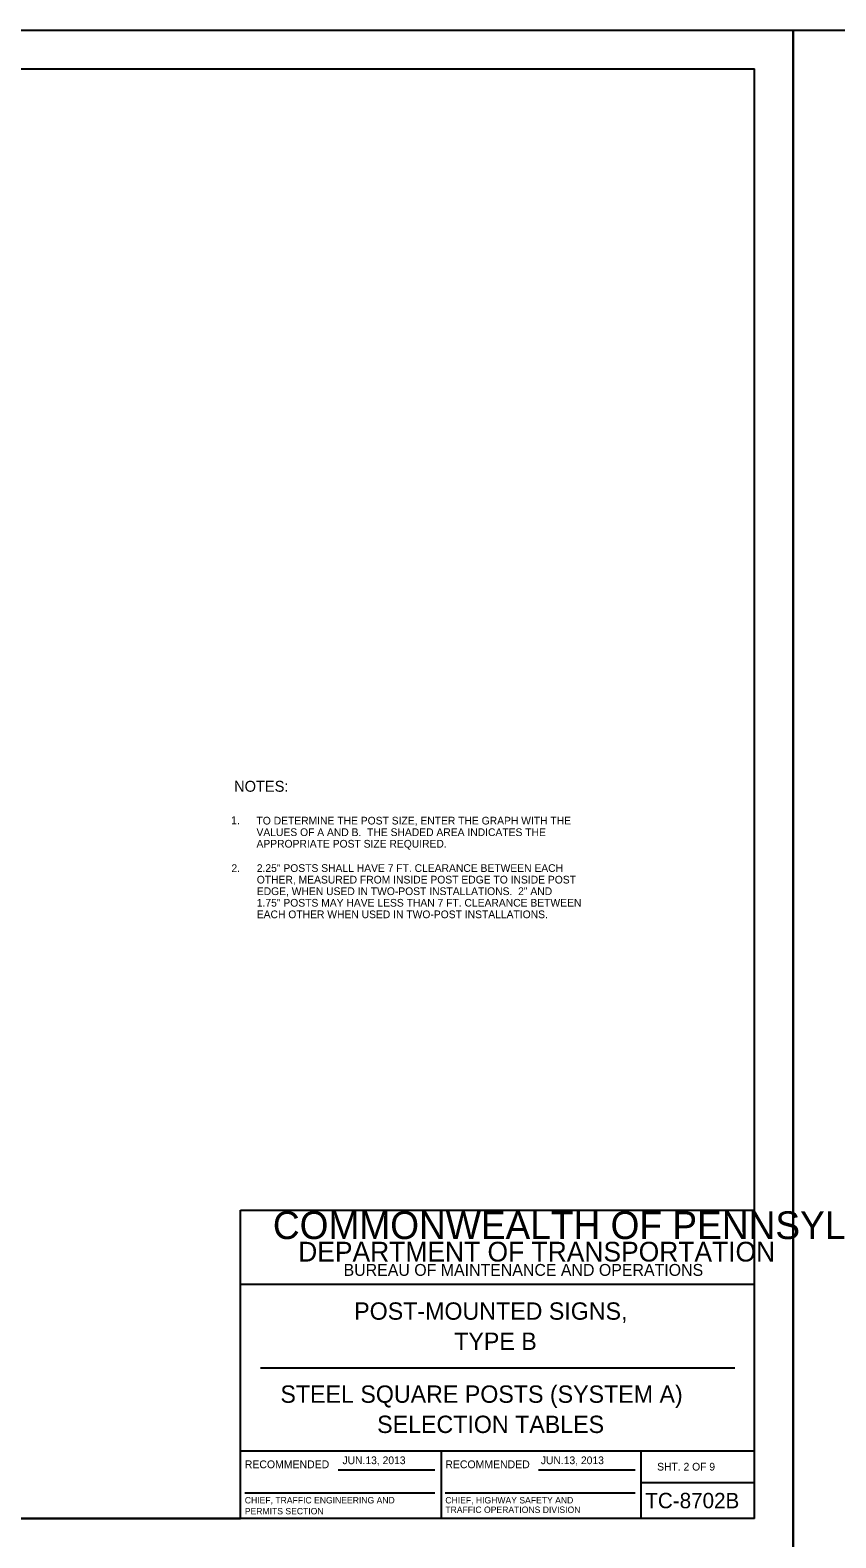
# Model space of a CAD drawing. Extents: x 644358 to 648627, y 294594 to 295782.
# Drawn here: x 645743 to 646057, y 295195 to 295782 of the extents above; entities that cross this region are included whole.
import ezdxf

# ---------------------------------------------------------------- set-up
doc = ezdxf.new("R2010")
doc.units = 0
for name, color, linetype in [('1', 7, 'Continuous'), ('2', 7, 'Continuous'), ('4', 7, 'Continuous'), ('PLT-BNDY', 7, 'Continuous')]:
    doc.layers.add(name, color=color, linetype=linetype)

msp = doc.modelspace()

# ---------------------------------------------------------------- linework, layer by layer
at = {"layer": '1'}
for p, q in [((645239.31, 295766.63), (646025.31, 295766.63)), ((646025.31, 295202.63), (646025.31, 295766.63)), ((645825.31, 295202.63), (645825.31, 295322.63)), ((645825.31, 295322.63), (646025.31, 295322.63)), ((646025.31, 295293.63), (645825.31, 295293.63)), ((645833.06, 295261.31), (646017.56, 295261.31)), ((645825.31, 295229), (646025.31, 295229)), ((645903.31, 295229), (645903.31, 295202.63)), ((645981.19, 295202.63), (645981.19, 295229)), ((645863.24, 295221.57), (645900.87, 295221.57)), ((645941.24, 295221.57), (645978.87, 295221.57)), ((645981.19, 295216.63), (646025.31, 295216.63)), ((645826.99, 295212.68), (645900.87, 295212.68)), ((645904.99, 295212.68), (645978.87, 295212.68)), ((646025.31, 295202.63), (645239.31, 295202.63)), ((645239.31, 295202.63), (645825.31, 295202.63))]:
    msp.add_line(p, q, dxfattribs=at)
at = {"layer": 'PLT-BNDY'}
for points in [[(645199.31, 295781.63), (646040.31, 295781.63), (646040.31, 295187.63), (645199.31, 295187.63)], [(646040.31, 295781.63), (646881.31, 295781.63), (646881.31, 295187.63), (646040.31, 295187.63)]]:
    msp.add_lwpolyline(points, close=True, dxfattribs=at)

# ---------------------------------------------------------------- texts
at = {"layer": '1'}
for s, height, p in [('1. ', 3.089, (645821.66, 295472.72)), ('2. ', 3, (645821.79, 295454.14)), ('COMMONWEALTH OF PENNSYLVANIA', 10.7828, (645837.9, 295311.36)), ('DEPARTMENT OF TRANSPORTATION', 7.6837, (645847.76, 295302.61)), ('BUREAU OF MAINTENANCE AND OPERATIONS', 4.6253, (645865.41, 295297.04)), ('POST-MOUNTED SIGNS,', 6.75, (645869.54, 295279.97)), ('TYPE B', 6.75, (645908.45, 295268.22)), ('STEEL SQUARE POSTS (SYSTEM A)', 6.75, (645840.84, 295247.66)), ('SELECTION TABLES', 6.75, (645878.47, 295235.91)), ('RECOMMENDED', 3.048, (645826.99, 295222.2)), ('RECOMMENDED', 3.048, (645904.99, 295222.2)), ('SHT. 2 OF 9', 3, (645987.39, 295221.31)), ('CHIEF, TRAFFIC ENGINEERING AND', 2.5, (645826.99, 295208.51)), ('CHIEF, HIGHWAY SAFETY AND', 2.5, (645904.99, 295208.51)), ('TC-8702B', 6, (645982.77, 295206.63)), ('PERMITS SECTION', 2.5, (645826.99, 295204.26)), ('TRAFFIC OPERATIONS DIVISION', 2.5, (645904.99, 295204.81))]:
    msp.add_text(s, height=height, dxfattribs=at).set_placement(p)
at = {"layer": '2'}
for s, p in [('TO DETERMINE THE POST SIZE, ENTER THE GRAPH WITH THE ', (645831.53, 295472.63)), ('VALUES OF A AND B.  THE SHADED AREA INDICATES THE', (645831.53, 295468.13)), ('APPROPRIATE POST SIZE REQUIRED.', (645831.53, 295463.63)), ('2.25" POSTS SHALL HAVE 7 FT. CLEARANCE BETWEEN EACH', (645831.65, 295454.17)), ('OTHER, MEASURED FROM INSIDE POST EDGE TO INSIDE POST', (645831.65, 295449.67)), ('1.75" POSTS MAY HAVE LESS THAN 7 FT. CLEARANCE BETWEEN', (645831.65, 295440.67)), ('EDGE, WHEN USED IN TWO-POST INSTALLATIONS.  2" AND', (645831.65, 295445.17)), ('EACH OTHER WHEN USED IN TWO-POST INSTALLATIONS.', (645831.65, 295436.17)), ('JUN.13, 2013', (645864.98, 295223.79)), ('JUN.13, 2013', (645942.14, 295223.79))]:
    msp.add_text(s, height=3, dxfattribs=at).set_placement(p)
at = {"layer": '4'}
msp.add_text('NOTES:', height=4.25, dxfattribs=at).set_placement((645822.82, 295485.36))

doc.saveas('drawing.dxf')
